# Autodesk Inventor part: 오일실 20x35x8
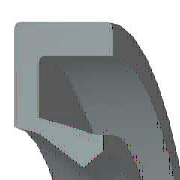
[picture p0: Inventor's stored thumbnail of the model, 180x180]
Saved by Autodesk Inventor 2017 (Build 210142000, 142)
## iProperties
IsCustomPart: 1
Created: 2012-02
Part Number: 오일실 20x35x8
Material: 고무
Description: 오일 실 - 비스프링, 조립 GA
Document SubType Name: Modeling
Standard: JIS B 2402
Designer: mdu-01
Standards Organization: JIS
Language: ko-KR
Size Designation: 20 35 8 A
Categories: <MemberInstance><Categories><Category DisplayName="샤프트 부품" InternalName="7f7aeb1f-a693-4053-b835-cee3144e0d98" Mnemonic="SHFT"><Category DisplayName="실링" Intern
Density: 0.93 g/cm^3
Appearance: Rubber-Black
Author: mdu-01
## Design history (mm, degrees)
body "Solid1"
revolve "회전1" stored, may be unused: angle "d27" = 360 deg
fillet "모깎기1" dims "d28" = 0.4 (= 0.05 x b)
sketch "스케치2"
  geometry: L1 (12.464, -6)-(13.214, -8); L2 (11.464, -5.5)-(12.464, -6); L3 (10, -2.2)-(11.464, -5.5); L4 (11.154, -1.2)-(10, -2.2); L5 (14.5, -7)-(11.154, -1.2); L6 (14.5, -0.4)-(14.5, -7); L7 (16, -0.4)-(14.5, -0.4); L8 (16, 0)-(16, -0.4); L9 (17.5, 0)-(16, 0); L10 (17.5, -8)-(17.5, 0); L11 (13.214, -8)-(17.5, -8); L12 (0, -9.6)-(0, 1.6) reference; L13 (28, 0)-(14, 0) reference
  constraints: 22 end point, 3 horizontal, 3 vertical
  dimensions: "d2" = 8 distance of L10.start L9.start (= b); "d4" = 1.5 distance of L9.start L8.start (= 0.1 x dd - 0.1 x Diam); "d6" = 0.4 distance of L8.start L7.start (= 0.05 x b); "d8" = 1.15385 horizontal distance of L4.start L3.start (= 0.0769231 x dd - 0.0769231 x Diam); "d10" = 1 vertical distance of L5.start L10.start (= 0.125 x b); "d12" = 1.5 distance of L7.start L6.start (= 0.1 x dd - 0.1 x Diam); "d14" = 0.8 vertical distance of L4.start L6.start (= 0.1 x b); "d16" = 4.28571 distance of L1.end L10.start (= 0.285714 x dd - 0.285714 x Diam); "d18" = 0.75 horizontal distance of L1.start L1.end (= 0.05 x dd - 0.05 x Diam); "d20" = 1 vertical distance of L4.start L3.start (= 0.125 x b); "d22" = 2 vertical distance of L1.start L1.end (= 0.25 x b); "d24" = 1 horizontal distance of L2.start L1.start (= 0.0666667 x dd - 0.0666667 x Diam); "d26" = 0.5 vertical distance of L2.start L1.start (= 0.0625 x b); "d29" = 0 distance between parallel lines of L13 L9; "d30" = 10 distance from line of L3.start L12 (= 0.5 x Diam); "d31" = 17.5 distance between parallel lines of L12 L10 (= 0.5 x dd)
other parameters: "dd" = 35 [user parameter; used in 7 equation terms], "b" = 8 [user parameter; used in 8 equation terms], "d1" = 8 (derived), "d3" = 2 (derived), "d5" = 0.4 (derived), "d7" = 1.53846 (derived), "d9" = 1 (derived), "d11" = 2 (derived), "d13" = 0.8 (derived), "d15" = 5.71429 (derived), "d17" = 1 (derived), "d19" = 1 (derived), "d21" = 2 (derived), "d23" = 1.33333 (derived), "d25" = 0.5 (derived), "d32" = 0
